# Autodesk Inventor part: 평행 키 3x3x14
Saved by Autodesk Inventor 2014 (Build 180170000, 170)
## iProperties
Created: 2026-06
Part Number: 평행 키 3x3x14
Material: 일반
Document SubType Name: Modeling
Designer: dg
Density: 1 g/cm^3
Appearance: 기본값
Author: dg
Author: jhkim
Description: 키 및 해당 키홈
Creation Date: 2026-05-29
Sending System: Autodesk Inventor 2027
Preprocessor: ST-DEVELOPER v20.1
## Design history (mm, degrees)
node "평행 키 3x3x141"
body "Solid1"
node "기준1"
